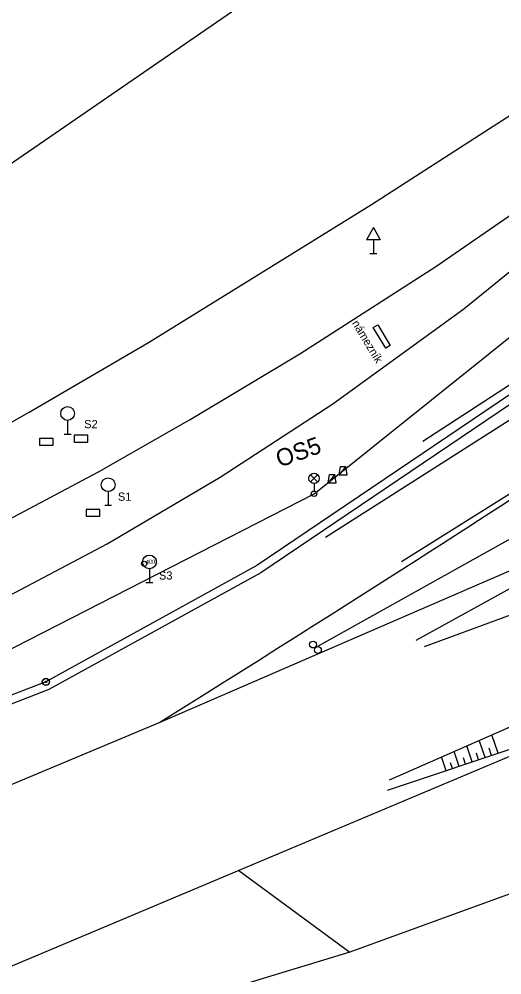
# Model space of a CAD drawing. Extents: x -734423 to 647242, y -1165906 to -111601.
# Drawn here: x -532656.7 to -532621.6, y -1114360.6 to -1114291 of the extents above; entities that cross this region are included whole.
import ezdxf

# ---------------------------------------------------------------- set-up
doc = ezdxf.new("R2010")
doc.units = 0
for name, color, linetype in [('Vrstva 13', 7, 'Continuous'), ('Vrstva 14', 7, 'Continuous'), ('Vrstva 15', 7, 'Continuous'), ('Vrstva 16', 7, 'Continuous'), ('Vrstva 18', 7, 'Continuous'), ('Vrstva 2', 7, 'Continuous'), ('Vrstva 21', 7, 'Continuous'), ('Vrstva 23', 7, 'Continuous'), ('Vrstva 24', 7, 'Continuous'), ('Vrstva 26', 7, 'Continuous'), ('Vrstva 8', 7, 'Continuous')]:
    doc.layers.add(name, color=color, linetype=linetype)

msp = doc.modelspace()

# ---------------------------------------------------------------- linework, layer by layer
at = {"layer": 'Vrstva 13'}
for p, q in [((-532609.334, -1114311.208), (-532639.126, -1114331.332)), ((-532639.126, -1114331.332), (-532654.569, -1114339.832)), ((-532654.569, -1114339.832), (-532674.044, -1114347.381))]:
    msp.add_line(p, q, dxfattribs=at)
msp.add_open_spline([(-532575.444, -1114280.959), (-532575.443, -1114283.433), (-532575.896, -1114285.972), (-532576.585, -1114288.447), (-532577.606, -1114292.135), (-532577.889, -1114296.195), (-532580.748, -1114298.956), (-532585.672, -1114303.695), (-532591.105, -1114306.8), (-532596.564, -1114310.307), (-532613.19, -1114320.97), (-532629.736, -1114331.763), (-532646.478, -1114342.245)], degree=3, dxfattribs=at)
at = {"layer": 'Vrstva 14'}
for p, q in [((-532624.995, -1114279.283), (-532673.031, -1114312.377)), ((-532609.649, -1114310.683), (-532639.409, -1114330.806)), ((-532593.924, -1114319.441), (-532646.478, -1114342.245)), ((-532564.202, -1114320.766), (-532640.726, -1114353.019)), ((-532639.409, -1114330.806), (-532654.776, -1114339.279)), ((-532654.776, -1114339.279), (-532681.033, -1114349.278)), ((-532646.478, -1114342.245), (-532677.974, -1114355.385)), ((-532593.454, -1114344.7), (-532632.632, -1114358.955)), ((-532640.726, -1114353.019), (-532688.399, -1114373.074)), ((-532640.726, -1114353.019), (-532632.632, -1114358.955)), ((-532632.632, -1114358.955), (-532653.371, -1114365.256))]:
    msp.add_line(p, q, dxfattribs=at)
at = {"layer": 'Vrstva 15'}
for p, q in [((-532622.88, -1114299.24), (-532614.45, -1114293.79)), ((-532631.07, -1114304.51), (-532622.88, -1114299.24)), ((-532639.41, -1114309.69), (-532631.07, -1114304.51)), ((-532626.38, -1114309.02), (-532619.33, -1114304.15)), ((-532630.93, -1114306.18), (-532631.43, -1114307.08)), ((-532630.93, -1114306.18), (-532630.43, -1114307.08)), ((-532624.34, -1114312.11), (-532617.26, -1114306.34)), ((-532630.43, -1114307.08), (-532631.43, -1114307.08)), ((-532630.93, -1114307.08), (-532630.93, -1114308.08)), ((-532631.18, -1114308.08), (-532630.68, -1114308.08)), ((-532636.28, -1114315.39), (-532626.38, -1114309.02)), ((-532647.31, -1114314.55), (-532639.41, -1114309.69)), ((-532633.88, -1114319.03), (-532624.34, -1114312.11)), ((-532655.99, -1114319.63), (-532647.31, -1114314.55)), ((-532644.26, -1114320.18), (-532636.28, -1114315.39)), ((-532642.08, -1114324.36), (-532633.88, -1114319.03)), ((-532664.84, -1114324.65), (-532655.99, -1114319.63)), ((-532653.19, -1114320.23), (-532653.19, -1114321.23)), ((-532650.94, -1114323.98), (-532644.26, -1114320.18)), ((-532653.44, -1114321.23), (-532652.94, -1114321.23)), ((-532662.27, -1114329.98), (-532650.94, -1114323.98)), ((-532650.31, -1114329.22), (-532642.08, -1114324.36)), ((-532635.514, -1114324.72), (-532634.986, -1114324.19)), ((-532635.514, -1114324.19), (-532634.986, -1114324.72)), ((-532650.24, -1114325.42), (-532650.24, -1114326.42)), ((-532635.25, -1114324.83), (-532635.25, -1114325.38)), ((-532650.49, -1114326.42), (-532649.99, -1114326.42)), ((-532659.88, -1114334.27), (-532650.31, -1114329.22)), ((-532647.24, -1114331.04), (-532647.24, -1114332.04)), ((-532647.49, -1114332.04), (-532646.99, -1114332.04))]:
    msp.add_line(p, q, dxfattribs=at)
for points in [[(-532630.613, -1114313.27), (-532629.708, -1114314.768), (-532630.029, -1114314.962), (-532630.934, -1114313.464)], [(-532655.24, -1114322.05), (-532654.24, -1114322.05), (-532654.24, -1114321.55), (-532655.24, -1114321.55)], [(-532652.72, -1114321.81), (-532651.72, -1114321.81), (-532651.72, -1114321.31), (-532652.72, -1114321.31)], [(-532633.43, -1114324.2), (-532633.33, -1114323.6), (-532632.93, -1114323.6)], [(-532634.23, -1114324.78), (-532634.13, -1114324.18), (-532633.73, -1114324.18)], [(-532651.85, -1114327.22), (-532650.85, -1114327.22), (-532650.85, -1114326.72), (-532651.85, -1114326.72)]]:
    msp.add_lwpolyline(points, close=True, dxfattribs=at)
for points in [[(-532633.43, -1114324.2), (-532632.83, -1114324.2), (-532632.93, -1114323.6)], [(-532634.23, -1114324.78), (-532633.63, -1114324.78), (-532633.73, -1114324.18)]]:
    msp.add_lwpolyline(points, dxfattribs=at)
for centre, radius in [((-532653.19, -1114319.73), 0.5), ((-532635.25, -1114324.455), 0.375), ((-532650.24, -1114324.92), 0.5), ((-532635.25, -1114325.58), 0.2), ((-532647.24, -1114330.54), 0.5), ((-532635.32, -1114336.56), 0.25), ((-532634.97, -1114336.96), 0.25)]:
    msp.add_circle(centre, radius, dxfattribs=at)
at = {"layer": 'Vrstva 16'}
msp.add_line((-532654.776, -1114339.279), (-532654.776, -1114339.279), dxfattribs=at)
for radius in [0.258, 0.25, 0.05, 0.05]:
    msp.add_circle((-532654.776, -1114339.279), radius, dxfattribs=at)
at = {"layer": 'Vrstva 18'}
for radius in [0.188, 0.00025]:
    msp.add_circle((-532647.62, -1114330.68), radius, dxfattribs=at)
at = {"layer": 'Vrstva 2'}
msp.add_lwpolyline([(-532846.625, -1114416.177), (-532848.108, -1114412.135), (-532808.842, -1114398.198), (-532780.05, -1114388.6), (-532754.69, -1114379.36), (-532726.64, -1114369.2), (-532698.29, -1114356.28), (-532677.56, -1114346.43), (-532659.12, -1114337.79), (-532635.25, -1114325.58), (-532614.01, -1114308.56), (-532586.09, -1114284.59), (-532565.53, -1114262.57), (-532540.97, -1114233.76), (-532534.452, -1114225.441), (-532535.662, -1114224.613)], dxfattribs=at)
at = {"layer": 'Vrstva 21'}
for p, q in [((-532597.37, -1114305.17), (-532634.41, -1114328.76)), ((-532628.89, -1114330.51), (-532615.79, -1114322.29)), ((-532610.73, -1114330.66), (-532627.24, -1114336.73)), ((-532629.75, -1114346.41), (-532618.3, -1114341.37))]:
    msp.add_line(p, q, dxfattribs=at)
at = {"layer": 'Vrstva 23'}
for p, q in [((-532596.66, -1114301.75), (-532627.32, -1114321.77)), ((-532627.82, -1114336.25), (-532601.84, -1114321.88)), ((-532599.38, -1114336.95), (-532629.93, -1114347.19)), ((-532622.792, -1114344.797), (-532623.216, -1114343.534)), ((-532621.844, -1114344.48), (-532622.297, -1114343.129)), ((-532623.74, -1114345.115), (-532624.135, -1114343.938)), ((-532622.318, -1114344.638), (-532622.493, -1114344.116)), ((-532625.636, -1114345.751), (-532625.973, -1114344.747)), ((-532624.688, -1114345.433), (-532625.053, -1114344.343)), ((-532624.214, -1114345.274), (-532624.366, -1114344.821)), ((-532623.266, -1114344.956), (-532623.43, -1114344.468)), ((-532625.162, -1114345.592), (-532625.303, -1114345.173))]:
    msp.add_line(p, q, dxfattribs=at)
at = {"layer": 'Vrstva 24'}
msp.add_lwpolyline([(-532581.66, -1114307.38), (-532608.03, -1114321.64), (-532635.16, -1114336.79)], dxfattribs=at)

# ---------------------------------------------------------------- texts
at = {"layer": 'Vrstva 18'}
msp.add_text(' 4001', height=0.3, dxfattribs=at).set_placement((-532647.62, -1114330.68))
at = {"layer": 'Vrstva 26'}
msp.add_text('námezník', height=0.6, rotation=301.1378, dxfattribs=at).set_placement((-532632.514, -1114313.153))
for s, p in [('S2', (-532651.986, -1114320.803)), ('S1', (-532649.531, -1114326.089)), ('S3', (-532646.54, -1114331.83))]:
    msp.add_text(s, height=0.6, dxfattribs=at).set_placement(p)
at = {"layer": 'Vrstva 8'}
msp.add_text('OS5', height=1.248, rotation=19.59463, dxfattribs=at).set_placement((-532637.761, -1114323.677))

doc.saveas('drawing.dxf')
